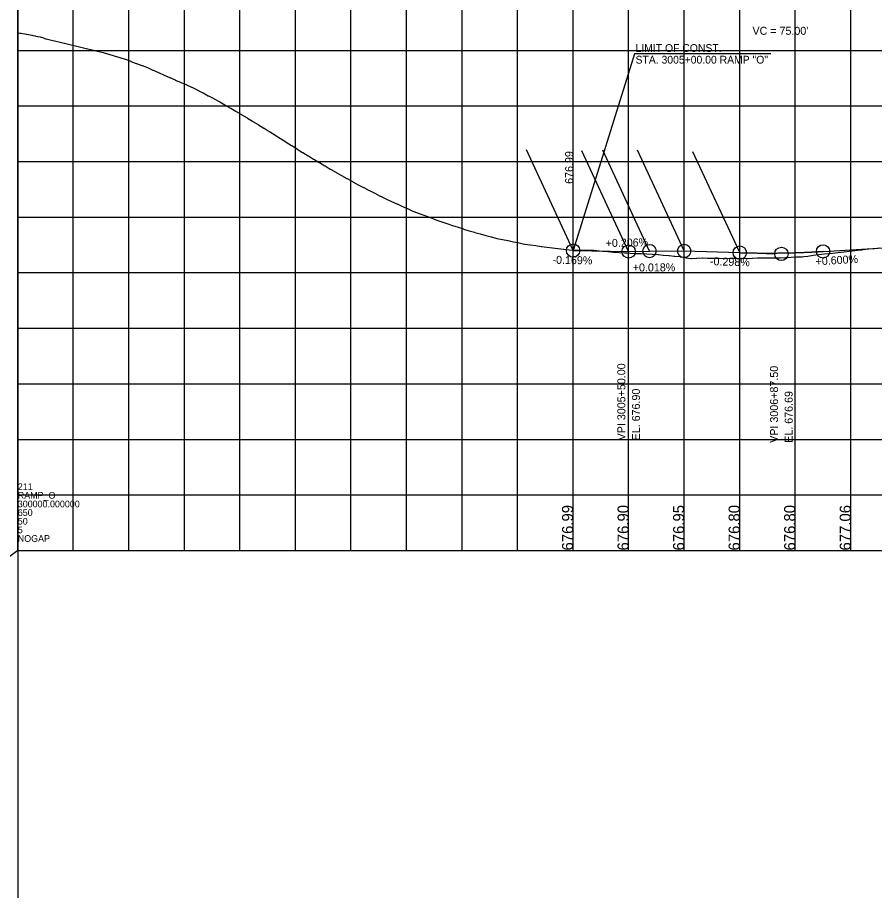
# Model space of a CAD drawing. Extents: x -7164 to 2214450, y -19642 to 253469.
# Drawn here: x 0 to 771, y 8694 to 9480 of the extents above; entities that cross this region are included whole.
import ezdxf

# ---------------------------------------------------------------- set-up
doc = ezdxf.new("R2010")
doc.units = 0
for name, color, linetype in [('DESIGN - PROFILE - Proposed', 7, 'Continuous'), ('DESIGN - PROFILE - Proposed Curve Text', 7, 'Continuous'), ('DESIGN - PROFILE - Proposed Text', 7, 'Continuous'), ('DESIGN - SCRATCH - User 1', 7, 'Continuous'), ('DESIGN - SHEET - Light Grid', 7, 'Continuous'), ('SURVEY - PROFILE - Ground Line with Text', 7, 'Continuous')]:
    doc.layers.add(name, color=color, linetype=linetype)

msp = doc.modelspace()

# ---------------------------------------------------------------- linework, layer by layer
at = {"layer": 'DESIGN - PROFILE - Proposed'}
for p, q in [((725, 9269.12), (792.5, 9273.17)), ((725, 9269.12), (792.5, 9273.17)), ((500, 9269.88), (550, 9269.04)), ((500, 9269.88), (550, 9269.04)), ((550, 9269.04), (568.75, 9269.43)), ((550, 9269.04), (568.75, 9269.43)), ((568.75, 9269.43), (600, 9269.48)), ((568.75, 9269.43), (600, 9269.48)), ((600, 9269.48), (650, 9267.99)), ((600, 9269.48), (650, 9267.99))]:
    msp.add_line(p, q, dxfattribs=at)
msp.add_spline([(650, 9267.99), (651.5, 9267.95), (653, 9267.91), (654.5, 9267.87), (656, 9267.83), (657.5, 9267.8), (659, 9267.77), (660.5, 9267.74), (662, 9267.72), (663.5, 9267.7), (665, 9267.68), (666.5, 9267.66), (668, 9267.65), (669.5, 9267.64), (671, 9267.63), (672.5, 9267.62), (674, 9267.62), (675.5, 9267.62), (677, 9267.62), (678.5, 9267.63), (680, 9267.64), (681.5, 9267.65), (683, 9267.66), (684.5, 9267.68), (686, 9267.69), (687.5, 9267.72), (689, 9267.74), (690.5, 9267.77), (692, 9267.8), (693.5, 9267.83), (695, 9267.86), (696.5, 9267.9), (698, 9267.94), (699.5, 9267.98), (701, 9268.03), (702.5, 9268.08), (704, 9268.13), (705.5, 9268.18), (707, 9268.24), (708.5, 9268.3), (710, 9268.36), (711.5, 9268.42), (713, 9268.49), (714.5, 9268.56), (716, 9268.63), (717.5, 9268.71), (719, 9268.79), (720.5, 9268.87), (722, 9268.95), (723.5, 9269.04), (725, 9269.12)], degree=3, dxfattribs=at)
msp.add_spline([(650, 9267.99), (651.5, 9267.95), (653, 9267.91), (654.5, 9267.87), (656, 9267.83), (657.5, 9267.8), (659, 9267.77), (660.5, 9267.74), (662, 9267.72), (663.5, 9267.7), (665, 9267.68), (666.5, 9267.66), (668, 9267.65), (669.5, 9267.64), (671, 9267.63), (672.5, 9267.62), (674, 9267.62), (675.5, 9267.62), (677, 9267.62), (678.5, 9267.63), (680, 9267.64), (681.5, 9267.65), (683, 9267.66), (684.5, 9267.68), (686, 9267.69), (687.5, 9267.72), (689, 9267.74), (690.5, 9267.77), (692, 9267.8), (693.5, 9267.83), (695, 9267.86), (696.5, 9267.9), (698, 9267.94), (699.5, 9267.98), (701, 9268.03), (702.5, 9268.08), (704, 9268.13), (705.5, 9268.18), (707, 9268.24), (708.5, 9268.3), (710, 9268.36), (711.5, 9268.42), (713, 9268.49), (714.5, 9268.56), (716, 9268.63), (717.5, 9268.71), (719, 9268.79), (720.5, 9268.87), (722, 9268.95), (723.5, 9269.04), (725, 9269.12)], degree=3, dxfattribs=at)
at = {"layer": 'DESIGN - PROFILE - Proposed Text'}
for p, q in [((555.2, 9446.86), (500, 9269.88)), ((555.2, 9446.86), (500, 9269.88)), ((677.91, 9446.86), (555.2, 9446.86)), ((677.91, 9446.86), (555.2, 9446.86)), ((650, 9267.99), (681.5, 9267.05)), ((650, 9267.99), (681.5, 9267.05)), ((725, 9269.12), (693.49, 9267.23)), ((725, 9269.12), (693.49, 9267.23))]:
    msp.add_line(p, q, dxfattribs=at)
for centre in [(500, 9269.88), (500, 9269.88), (550, 9269.04), (550, 9269.04), (568.75, 9269.43), (568.75, 9269.43), (600, 9269.48), (600, 9269.48), (650, 9267.99), (650, 9267.99), (687.5, 9266.87), (687.5, 9266.87), (725, 9269.12), (725, 9269.12)]:
    msp.add_circle(centre, 6, dxfattribs=at)
at = {"layer": 'DESIGN - SCRATCH - User 1'}
for p, q in [((0, 10000), (0, 9000)), ((0, 10000), (0, 9000)), ((500, 9269.88), (457.9, 9360.59)), ((500, 9269.88), (457.9, 9360.59)), ((500, 9269.88), (457.9, 9360.59)), ((500, 9269.88), (457.9, 9360.59)), ((550, 9269.04), (507.9, 9359.75)), ((550, 9269.04), (507.9, 9359.75)), ((568.75, 9269.43), (526.65, 9360.13)), ((568.75, 9269.43), (526.65, 9360.13)), ((600, 9269.48), (557.9, 9360.19)), ((600, 9269.48), (557.9, 9360.19)), ((650, 9267.99), (607.9, 9358.7)), ((650, 9267.99), (607.9, 9358.7)), ((0, 9000), (-6163.52, 4357.51)), ((0, 9000), (-6163.52, 4357.51)), ((0, 9000), (2600, 9000)), ((0, 9000), (2600, 9000))]:
    msp.add_line(p, q, dxfattribs=at)
for points in [[(0, 9000), (1306.85, 9000), (1306.85, 10000)], [(0, 9000), (1306.85, 9000), (1306.85, 10000)], [(500, 9000), (500, 10000)], [(500, 9000), (500, 10000)]]:
    msp.add_lwpolyline(points, dxfattribs=at)
at = {"layer": 'DESIGN - SHEET - Light Grid'}
for p, q in [((0, 9000), (0, 11500)), ((0, 9000), (0, 11500)), ((50, 9000), (50, 10000)), ((50, 9000), (50, 10000)), ((100, 9000), (100, 10000)), ((100, 9000), (100, 10000)), ((150, 9000), (150, 10000)), ((150, 9000), (150, 10000)), ((200, 9000), (200, 10000)), ((200, 9000), (200, 10000)), ((250, 9000), (250, 10000)), ((250, 9000), (250, 10000)), ((300, 9000), (300, 10000)), ((300, 9000), (300, 10000)), ((350, 9000), (350, 10000)), ((350, 9000), (350, 10000)), ((400, 9000), (400, 10000)), ((400, 9000), (400, 10000)), ((450, 9000), (450, 10000)), ((450, 9000), (450, 10000)), ((500, 9000), (500, 10000)), ((500, 9000), (500, 10000)), ((550, 9000), (550, 10000)), ((550, 9000), (550, 10000)), ((600, 9000), (600, 10000)), ((600, 9000), (600, 10000)), ((650, 9000), (650, 10000)), ((650, 9000), (650, 10000)), ((700, 9000), (700, 10000)), ((700, 9000), (700, 10000)), ((750, 9000), (750, 10000)), ((750, 9000), (750, 10000)), ((0, 9450), (2600, 9450)), ((0, 9450), (2600, 9450)), ((0, 9400), (2600, 9400)), ((0, 9400), (2600, 9400)), ((0, 9350), (2600, 9350)), ((0, 9350), (2600, 9350)), ((0, 9300), (2600, 9300)), ((0, 9300), (2600, 9300)), ((0, 9250), (2600, 9250)), ((0, 9250), (2600, 9250)), ((0, 9200), (2600, 9200)), ((0, 9200), (2600, 9200)), ((0, 9150), (2600, 9150)), ((0, 9150), (2600, 9150)), ((0, 9100), (2600, 9100)), ((0, 9100), (2600, 9100)), ((0, 9050), (2600, 9050)), ((0, 9050), (2600, 9050)), ((0, 9000), (1600, 9000)), ((0, 9000), (0, 6500)), ((0, 9000), (1600, 9000)), ((0, 9000), (0, 6500))]:
    msp.add_line(p, q, dxfattribs=at)
at = {"layer": 'SURVEY - PROFILE - Ground Line with Text'}
for points in [[(0, 9465.76), (1.71, 9465.53), (2.22, 9465.49), (2.53, 9465.38), (2.96, 9465.47), (3.1, 9465.46), (7.76, 9464.55), (7.9, 9464.5), (8.19, 9464.46), (12.59, 9463.6), (12.86, 9463.56), (13.46, 9463.54), (15.79, 9463.05), (16.22, 9462.93), (17.8, 9462.54), (18.44, 9462.46), (20.07, 9462.31), (23.06, 9461.41), (24.89, 9460.52), (25.33, 9460.41), (25.47, 9460.39), (30.37, 9459.27), (30.43, 9459.27), (34.38, 9458.36), (36.86, 9457.63), (36.88, 9457.62), (41.83, 9456.46), (41.87, 9456.45), (41.91, 9456.44), (46.87, 9455.27), (46.92, 9455.26), (51.87, 9454.1), (51.92, 9454.09), (56.84, 9452.93), (56.9, 9452.92), (61.56, 9451.84), (61.84, 9451.77), (66.83, 9450.59), (66.85, 9450.58), (71.81, 9449.41), (71.85, 9449.4), (76.79, 9448.23), (76.85, 9448.21), (81.79, 9446.69), (81.85, 9446.67), (86.78, 9445.15), (86.85, 9445.13), (91.77, 9443.61), (91.84, 9443.59), (96.77, 9442.07), (96.84, 9442.04), (101.75, 9440.18), (101.85, 9440.14), (106.72, 9438.29), (106.85, 9438.25), (111.7, 9436.41), (111.85, 9436.36), (116.68, 9434.52), (116.85, 9434.47), (121.69, 9432.28), (121.84, 9432.22), (126.7, 9430.03), (126.83, 9429.97), (131.71, 9427.77), (131.82, 9427.72), (136.72, 9425.5), (136.82, 9425.46), (141.68, 9423.39), (141.82, 9423.33), (146.64, 9421.27), (146.82, 9421.2), (151.6, 9419.16), (151.82, 9419.06), (156.55, 9417.04), (156.81, 9416.92), (161.52, 9414.44), (161.81, 9414.3), (166.49, 9411.83), (166.8, 9411.68), (171.46, 9409.23), (171.8, 9409.04), (176.43, 9406.61), (176.8, 9406.4), (181.4, 9403.98), (181.8, 9403.76), (186.41, 9401.05), (186.78, 9400.84), (191.42, 9398.12), (191.77, 9397.92), (196.42, 9395.18), (196.76, 9395), (201.43, 9392.25), (201.74, 9392.06), (206.44, 9389.3), (206.73, 9389.12), (206.75, 9389.11), (211.47, 9386.22), (211.74, 9386.05), (216.47, 9383.16), (216.73, 9383), (221.47, 9380.09)], [(0, 9465.76), (1.71, 9465.53), (2.22, 9465.49), (2.53, 9465.38), (2.96, 9465.47), (3.1, 9465.46), (7.76, 9464.55), (7.9, 9464.5), (8.19, 9464.46), (12.59, 9463.6), (12.86, 9463.56), (13.46, 9463.54), (15.79, 9463.05), (16.22, 9462.93), (17.8, 9462.54), (18.44, 9462.46), (20.07, 9462.31), (23.06, 9461.41), (24.89, 9460.52), (25.33, 9460.41), (25.47, 9460.39), (30.37, 9459.27), (30.43, 9459.27), (34.38, 9458.36), (36.86, 9457.63), (36.88, 9457.62), (41.83, 9456.46), (41.87, 9456.45), (41.91, 9456.44), (46.87, 9455.27), (46.92, 9455.26), (51.87, 9454.1), (51.92, 9454.09), (56.84, 9452.93), (56.9, 9452.92), (61.56, 9451.84), (61.84, 9451.77), (66.83, 9450.59), (66.85, 9450.58), (71.81, 9449.41), (71.85, 9449.4), (76.79, 9448.23), (76.85, 9448.21), (81.79, 9446.69), (81.85, 9446.67), (86.78, 9445.15), (86.85, 9445.13), (91.77, 9443.61), (91.84, 9443.59), (96.77, 9442.07), (96.84, 9442.04), (101.75, 9440.18), (101.85, 9440.14), (106.72, 9438.29), (106.85, 9438.25), (111.7, 9436.41), (111.85, 9436.36), (116.68, 9434.52), (116.85, 9434.47), (121.69, 9432.28), (121.84, 9432.22), (126.7, 9430.03), (126.83, 9429.97), (131.71, 9427.77), (131.82, 9427.72), (136.72, 9425.5), (136.82, 9425.46), (141.68, 9423.39), (141.82, 9423.33), (146.64, 9421.27), (146.82, 9421.2), (151.6, 9419.16), (151.82, 9419.06), (156.55, 9417.04), (156.81, 9416.92), (161.52, 9414.44), (161.81, 9414.3), (166.49, 9411.83), (166.8, 9411.68), (171.46, 9409.23), (171.8, 9409.04), (176.43, 9406.61), (176.8, 9406.4), (181.4, 9403.98), (181.8, 9403.76), (186.41, 9401.05), (186.78, 9400.84), (191.42, 9398.12), (191.77, 9397.92), (196.42, 9395.18), (196.76, 9395), (201.43, 9392.25), (201.74, 9392.06), (206.44, 9389.3), (206.73, 9389.12), (206.75, 9389.11), (211.47, 9386.22), (211.74, 9386.05), (216.47, 9383.16), (216.73, 9383), (221.47, 9380.09)], [(221.47, 9380.09), (221.72, 9379.94), (226.47, 9377.03), (226.7, 9376.89), (231.47, 9373.97), (231.68, 9373.84), (236.45, 9370.82), (236.68, 9370.68), (241.43, 9367.66), (241.67, 9367.52), (246.42, 9364.5), (246.66, 9364.35), (251.4, 9361.34), (251.65, 9361.19), (256.38, 9358.19), (256.64, 9358.03), (261.37, 9355.17), (261.63, 9355.01), (266.36, 9352.16), (266.63, 9351.99), (271.34, 9349.14), (271.62, 9348.98), (276.33, 9346.14), (276.61, 9345.97), (281.32, 9343.13), (281.6, 9342.97), (286.32, 9340.33), (286.59, 9340.17), (291.31, 9337.54), (291.58, 9337.38), (296.31, 9334.74), (296.57, 9334.59), (296.58, 9334.59), (301.32, 9331.94), (301.57, 9331.81), (306.32, 9329.16), (306.57, 9329.04), (311.33, 9326.6), (311.56, 9326.48), (316.33, 9324.05), (316.55, 9323.93), (321.33, 9321.49), (321.54, 9321.38), (326.33, 9318.93), (326.53, 9318.83), (331.34, 9316.38), (331.52, 9316.28), (336.35, 9314.1), (336.51, 9314.02), (341.36, 9311.84), (341.5, 9311.77), (346.38, 9309.57), (346.49, 9309.52), (351.39, 9307.32), (351.48, 9307.28), (356.4, 9305.06), (356.47, 9305.03), (361.41, 9303.2), (361.46, 9303.18), (366.42, 9301.35), (366.45, 9301.33), (371.42, 9299.5), (371.45, 9299.48), (376.43, 9297.65), (376.44, 9297.64), (381, 9295.96), (381.43, 9295.8), (381.73, 9295.7), (386.41, 9294.17), (386.43, 9294.16), (391.4, 9292.54), (391.43, 9292.53), (396.38, 9290.91), (396.43, 9290.9), (401.36, 9289.28), (401.43, 9289.26), (406.35, 9287.66), (406.43, 9287.63), (411.34, 9286.29), (411.43, 9286.27), (416.34, 9284.93), (416.43, 9284.91), (421.33, 9283.57), (421.43, 9283.54), (426.33, 9282.21), (426.43, 9282.18), (431.32, 9280.84), (431.43, 9280.81), (436.33, 9279.82), (436.44, 9279.8), (441.34, 9278.8), (441.43, 9278.78), (446.34, 9277.78), (446.43, 9277.76), (451.34, 9276.76), (451.43, 9276.75), (456.35, 9275.74), (456.43, 9275.73), (461.35, 9275.05), (461.42, 9275.04), (466.36, 9274.36)], [(221.47, 9380.09), (221.72, 9379.94), (226.47, 9377.03), (226.7, 9376.89), (231.47, 9373.97), (231.68, 9373.84), (236.45, 9370.82), (236.68, 9370.68), (241.43, 9367.66), (241.67, 9367.52), (246.42, 9364.5), (246.66, 9364.35), (251.4, 9361.34), (251.65, 9361.19), (256.38, 9358.19), (256.64, 9358.03), (261.37, 9355.17), (261.63, 9355.01), (266.36, 9352.16), (266.63, 9351.99), (271.34, 9349.14), (271.62, 9348.98), (276.33, 9346.14), (276.61, 9345.97), (281.32, 9343.13), (281.6, 9342.97), (286.32, 9340.33), (286.59, 9340.17), (291.31, 9337.54), (291.58, 9337.38), (296.31, 9334.74), (296.57, 9334.59), (296.58, 9334.59), (301.32, 9331.94), (301.57, 9331.81), (306.32, 9329.16), (306.57, 9329.04), (311.33, 9326.6), (311.56, 9326.48), (316.33, 9324.05), (316.55, 9323.93), (321.33, 9321.49), (321.54, 9321.38), (326.33, 9318.93), (326.53, 9318.83), (331.34, 9316.38), (331.52, 9316.28), (336.35, 9314.1), (336.51, 9314.02), (341.36, 9311.84), (341.5, 9311.77), (346.38, 9309.57), (346.49, 9309.52), (351.39, 9307.32), (351.48, 9307.28), (356.4, 9305.06), (356.47, 9305.03), (361.41, 9303.2), (361.46, 9303.18), (366.42, 9301.35), (366.45, 9301.33), (371.42, 9299.5), (371.45, 9299.48), (376.43, 9297.65), (376.44, 9297.64), (381, 9295.96), (381.43, 9295.8), (381.73, 9295.7), (386.41, 9294.17), (386.43, 9294.16), (391.4, 9292.54), (391.43, 9292.53), (396.38, 9290.91), (396.43, 9290.9), (401.36, 9289.28), (401.43, 9289.26), (406.35, 9287.66), (406.43, 9287.63), (411.34, 9286.29), (411.43, 9286.27), (416.34, 9284.93), (416.43, 9284.91), (421.33, 9283.57), (421.43, 9283.54), (426.33, 9282.21), (426.43, 9282.18), (431.32, 9280.84), (431.43, 9280.81), (436.33, 9279.82), (436.44, 9279.8), (441.34, 9278.8), (441.43, 9278.78), (446.34, 9277.78), (446.43, 9277.76), (451.34, 9276.76), (451.43, 9276.75), (456.35, 9275.74), (456.43, 9275.73), (461.35, 9275.05), (461.42, 9275.04), (466.36, 9274.36)], [(466.36, 9274.36), (466.42, 9274.35), (471.36, 9273.67), (471.42, 9273.66), (476.37, 9272.97), (476.42, 9272.97), (481.37, 9272.28), (481.42, 9272.28), (486.38, 9271.72), (486.41, 9271.71), (491.39, 9271.15), (491.41, 9271.15), (496.4, 9270.59), (500, 9270.18), (504.99, 9270.25), (505.01, 9270.25), (509.99, 9270.31), (510.01, 9270.31), (514.99, 9270.37), (515.01, 9270.37), (516.33, 9270.38), (521.31, 9269.92), (521.33, 9269.92), (526.31, 9269.46), (526.33, 9269.45), (531.31, 9268.95), (531.33, 9268.95), (536.32, 9268.44), (541.32, 9268.19), (541.33, 9268.19), (546.32, 9267.93), (548.74, 9267.8), (551.33, 9267.66), (551.34, 9267.66), (556.28, 9267.37), (556.39, 9267.36), (561.27, 9267.13), (561.4, 9267.13), (566.24, 9266.88), (566.44, 9266.87), (571.23, 9266.65), (571.44, 9266.63), (576.22, 9266.4), (576.47, 9266.38), (581.19, 9265.86), (581.47, 9265.84), (586.12, 9265.32), (586.51, 9265.28), (591.12, 9264.86), (591.51, 9264.82), (596.1, 9264.38), (596.53, 9264.34), (601.1, 9263.51), (601.53, 9263.46), (606.09, 9262.62), (606.54, 9262.62), (611.09, 9262.92), (611.54, 9262.92), (616.07, 9263.21), (616.56, 9263.21), (621.07, 9263.13), (621.56, 9263.13), (626.06, 9263.03), (626.57, 9263.03), (631.07, 9262.93), (631.53, 9262.95), (636.05, 9262.83), (636.52, 9262.86), (641.06, 9262.88), (641.51, 9262.9), (646.07, 9262.91), (646.51, 9262.93), (651.08, 9262.87), (651.5, 9262.89), (656.07, 9262.83), (656.49, 9262.84), (661.09, 9263.04), (661.47, 9263.05), (666.1, 9263.24), (666.45, 9263.25), (671.13, 9263.29), (671.41, 9263.3), (676.15, 9263.33), (676.39, 9263.34), (681.15, 9263.37), (681.36, 9263.37), (686.13, 9263.4), (686.36, 9263.41), (691.17, 9263.64), (691.31, 9263.65), (696.2, 9263.88), (696.27, 9263.88), (701.22, 9264.12), (701.25, 9264.12), (706.22, 9264.36), (706.24, 9264.36), (707.77, 9264.55), (711.22, 9264.97), (711.24, 9264.97), (716.21, 9265.58), (716.24, 9265.59)], [(466.36, 9274.36), (466.42, 9274.35), (471.36, 9273.67), (471.42, 9273.66), (476.37, 9272.97), (476.42, 9272.97), (481.37, 9272.28), (481.42, 9272.28), (486.38, 9271.72), (486.41, 9271.71), (491.39, 9271.15), (491.41, 9271.15), (496.4, 9270.59), (500, 9270.18), (504.99, 9270.25), (505.01, 9270.25), (509.99, 9270.31), (510.01, 9270.31), (514.99, 9270.37), (515.01, 9270.37), (516.33, 9270.38), (521.31, 9269.92), (521.33, 9269.92), (526.31, 9269.46), (526.33, 9269.45), (531.31, 9268.95), (531.33, 9268.95), (536.32, 9268.44), (541.32, 9268.19), (541.33, 9268.19), (546.32, 9267.93), (548.74, 9267.8), (551.33, 9267.66), (551.34, 9267.66), (556.28, 9267.37), (556.39, 9267.36), (561.27, 9267.13), (561.4, 9267.13), (566.24, 9266.88), (566.44, 9266.87), (571.23, 9266.65), (571.44, 9266.63), (576.22, 9266.4), (576.47, 9266.38), (581.19, 9265.86), (581.47, 9265.84), (586.12, 9265.32), (586.51, 9265.28), (591.12, 9264.86), (591.51, 9264.82), (596.1, 9264.38), (596.53, 9264.34), (601.1, 9263.51), (601.53, 9263.46), (606.09, 9262.62), (606.54, 9262.62), (611.09, 9262.92), (611.54, 9262.92), (616.07, 9263.21), (616.56, 9263.21), (621.07, 9263.13), (621.56, 9263.13), (626.06, 9263.03), (626.57, 9263.03), (631.07, 9262.93), (631.53, 9262.95), (636.05, 9262.83), (636.52, 9262.86), (641.06, 9262.88), (641.51, 9262.9), (646.07, 9262.91), (646.51, 9262.93), (651.08, 9262.87), (651.5, 9262.89), (656.07, 9262.83), (656.49, 9262.84), (661.09, 9263.04), (661.47, 9263.05), (666.1, 9263.24), (666.45, 9263.25), (671.13, 9263.29), (671.41, 9263.3), (676.15, 9263.33), (676.39, 9263.34), (681.15, 9263.37), (681.36, 9263.37), (686.13, 9263.4), (686.36, 9263.41), (691.17, 9263.64), (691.31, 9263.65), (696.2, 9263.88), (696.27, 9263.88), (701.22, 9264.12), (701.25, 9264.12), (706.22, 9264.36), (706.24, 9264.36), (707.77, 9264.55), (711.22, 9264.97), (711.24, 9264.97), (716.21, 9265.58), (716.24, 9265.59)], [(716.24, 9265.59), (721.21, 9266.19), (721.24, 9266.19), (726.22, 9266.78), (726.24, 9266.78), (731.2, 9267.31), (731.24, 9267.31), (736.18, 9267.82), (736.24, 9267.83), (741.15, 9268.43), (741.25, 9268.45), (746.12, 9269.04), (746.26, 9269.06), (751.09, 9269.61), (751.26, 9269.63), (756.06, 9270.17), (756.27, 9270.19), (759.98, 9270.61), (761.04, 9270.73), (761.27, 9270.75), (766.03, 9271.28), (766.27, 9271.3), (770.99, 9271.83), (771.27, 9271.85), (775.96, 9272.37)], [(716.24, 9265.59), (721.21, 9266.19), (721.24, 9266.19), (726.22, 9266.78), (726.24, 9266.78), (731.2, 9267.31), (731.24, 9267.31), (736.18, 9267.82), (736.24, 9267.83), (741.15, 9268.43), (741.25, 9268.45), (746.12, 9269.04), (746.26, 9269.06), (751.09, 9269.61), (751.26, 9269.63), (756.06, 9270.17), (756.27, 9270.19), (759.98, 9270.61), (761.04, 9270.73), (761.27, 9270.75), (766.03, 9271.28), (766.27, 9271.3), (770.99, 9271.83), (771.27, 9271.85), (775.96, 9272.37)]]:
    msp.add_lwpolyline(points, dxfattribs=at)

# ---------------------------------------------------------------- texts
at = {"layer": 'DESIGN - PROFILE - Proposed Curve Text'}
msp.add_text("VC = 75.00'", height=7.2, dxfattribs=at).set_placement((661.48, 9464.02))
msp.add_text("VC = 75.00'", height=7.2, dxfattribs=at).set_placement((661.48, 9464.02))
for s, p in [('676.99', (500, 9329.88)), ('676.99', (500, 9329.88)), ('VPI 3005+50.00', (547, 9099.04)), ('VPI 3005+50.00', (547, 9099.04)), ('VPI 3006+87.50', (684.5, 9096.87)), ('VPI 3006+87.50', (684.5, 9096.87)), ('EL. 676.90', (560.2, 9099.04)), ('EL. 676.90', (560.2, 9099.04)), ('EL. 676.69', (697.7, 9096.87)), ('EL. 676.69', (697.7, 9096.87))]:
    msp.add_text(s, height=7.2, rotation=90, dxfattribs=at).set_placement(p)
at = {"layer": 'DESIGN - PROFILE - Proposed Text'}
for s, p in [('LIMIT OF CONST.', (556.2, 9448.61)), ('LIMIT OF CONST.', (556.2, 9448.61)), ('STA. 3005+00.00 RAMP "O"', (556.2, 9438.11)), ('STA. 3005+00.00 RAMP "O"', (556.2, 9438.11))]:
    msp.add_text(s, height=7, dxfattribs=at).set_placement(p)
for s, height, rotation, p in [('+0.206%', 7.2, 1.17936, (529.36, 9272.99)), ('+0.206%', 7.2, 1.17936, (529.36, 9272.99)), ('-0.169%', 7.2, 359.03408, (481.39, 9257.99)), ('-0.169%', 7.2, 359.03408, (481.39, 9257.99)), ('-0.298%', 7.2, 358.29436, (623.14, 9256.72)), ('-0.298%', 7.2, 358.29436, (623.14, 9256.72)), ('+0.600%', 7.2, 3.43363, (718.5, 9256.51)), ('+0.600%', 7.2, 3.43363, (718.5, 9256.51)), ('+0.018%', 7.2, 0.10084, (553.7, 9251.05)), ('+0.018%', 7.2, 0.10084, (553.7, 9251.05)), ('676.99', 10, 90, (500, 9000)), ('676.99', 10, 90, (500, 9000)), ('676.90', 10, 90, (550, 9000)), ('676.90', 10, 90, (550, 9000)), ('676.95', 10, 90, (600, 9000)), ('676.95', 10, 90, (600, 9000)), ('676.80', 10, 90, (650, 9000)), ('676.80', 10, 90, (650, 9000)), ('676.80', 10, 90, (700, 9000)), ('676.80', 10, 90, (700, 9000)), ('677.06', 10, 90, (750, 9000)), ('677.06', 10, 90, (750, 9000))]:
    msp.add_text(s, height=height, rotation=rotation, dxfattribs=at).set_placement(p)
at = {"layer": 'DESIGN - SHEET - Light Grid'}
for s, p in [('211', (0, 9054.36)), ('211', (0, 9054.36)), ('RAMP_O', (0, 9046.59)), ('RAMP_O', (0, 9046.59)), ('300000.000000', (0, 9038.83)), ('300000.000000', (0, 9038.83)), ('650', (0, 9031.06)), ('650', (0, 9031.06)), ('50', (0, 9023.3)), ('50', (0, 9023.3)), ('5', (0, 9015.53)), ('5', (0, 9015.53)), ('NOGAP', (0, 9007.77)), ('NOGAP', (0, 9007.77))]:
    msp.add_text(s, height=6, dxfattribs=at).set_placement(p)

doc.saveas('drawing.dxf')
